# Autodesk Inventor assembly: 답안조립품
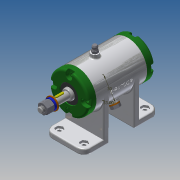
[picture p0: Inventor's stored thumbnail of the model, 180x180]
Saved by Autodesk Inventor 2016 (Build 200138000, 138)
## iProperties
Created: 2017-02
Part Number: 답안조립품
Document SubType Name: Assembly
Designer: Administrator
Author: Administrator
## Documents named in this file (16)
- D:\470208V1005\답안조립품.iam
- D:\470208V1005\본체.ipt
- D:\470208V1005\V벨트풀리.ipt
- D:\470208V1005\너트 M 8.ipt
- D:\470208V1005\니플 M 6 x 0.75.ipt
- D:\470208V1005\뒤커버.ipt
- D:\470208V1005\베어링 15 x 32 x 9.ipt
- D:\470208V1005\볼트 M 6 x 8.ipt
- D:\470208V1005\볼트 M4 x 12.ipt
- D:\470208V1005\스프링와셔 8.ipt
- D:\470208V1005\앞커버.ipt
- D:\470208V1005\오일 실 15 25 7.ipt
- D:\470208V1005\와셔 6x11.5.ipt
- D:\470208V1005\와셔 8x17.ipt
- D:\470208V1005\축.ipt
- D:\470208V1005\키 3 x 3 x 12.ipt
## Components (11 placed, 3 different names)
1. V벨트풀리:1
2. KS B 2023 6002 - 15 x 32 x 9:1
3. KS B 2023 6002 - 15 x 32 x 9:2
4. ISO 4762 M4 x 12:1
5. ISO 4762 M4 x 12:2
6. ISO 4762 M4 x 12:3
7. ISO 4762 M4 x 12:4
8. ISO 4762 M4 x 12:5
9. ISO 4762 M4 x 12:6
10. ISO 4762 M4 x 12:7
11. ISO 4762 M4 x 12:8
